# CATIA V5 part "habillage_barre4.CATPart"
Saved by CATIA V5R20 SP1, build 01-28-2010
Part number: habillage_barre4
Bounding box of the stored display mesh (mm): x -20 to 0, y -1003.224 to -170.237, z 31.642 to 358.692
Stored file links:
  C:\Users\patrice\Desktop\IFMa\Semestre 3\IAO\projet iao\iao\habillage_barre4.CATPart
  C:\Users\patrice\Desktop\IFMa\Semestre 3\IAO\projet iao\iao\pcabanel.CATProduct
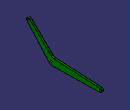
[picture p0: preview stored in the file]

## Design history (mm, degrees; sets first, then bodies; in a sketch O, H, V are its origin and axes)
External parameters (linked from other documents)
  External.AC = 200 mm
Set1
  Plane1: linked copy from another document
  Point1 "C": linked copy from another document
  Point2 "G": linked copy from another document
  Point3 "B": linked copy from another document
Body1 (main body)
  Sketch1 on Plane1, origin (0, 0, 0), H (0, 1, 0), V (0, 0, 1)
    line L1 (-189.8267, 41.8071) -> (-718.3338, 31.6418)
    point P2 (-736.7571, 31.2874)
    line L2 (-748.9992, 45.0596) -> (-998.2085, 325.4151)
    arc A1 centre (-983.2604, 338.7025) radius 20 from (-998.2085, 325.4151) to (-969.3804, 353.102) cw
    point P4 (-983.2604, 338.7025)
    line L3 (-969.3804, 353.102) -> (-726.3262, 118.8166)
    point P6 (-715.5445, 108.4238)
    line L4 (-700.5886, 107.6667) -> (-189.2001, 81.7778)
    arc A2 centre (-190.2113, 61.8034) radius 20 from (-189.2001, 81.7778) to (-189.8267, 41.8071) cw
    point P8 (-190.2113, 61.8034)
    reference projected point E1 (-190.2113, 61.8034) from Point1
    reference projected point E2 (-983.2604, 338.7025) from Point2
    construction line L5 (-715.5445, 108.4238) -> (-736.7571, 31.2874)
    reference projected point E3 (-726.1508, 69.8556) from Point3
    arc A3 centre (-719.1031, 71.6344) radius 40 from (-748.9992, 45.0596) to (-718.3338, 31.6418) ccw
    arc A4 centre (-698.5662, 147.6155) radius 40 from (-726.3262, 118.8166) to (-700.5886, 107.6667) ccw
    radius A1 = 20 {= 0.1*External.AC}
    radius A2 = 20 {= 0.1*External.AC}
    length L5 = 80 {= External.AC /2.5}
    angle L4 L1 = 4
    radius A3 = 40 {= External.AC /5}
    radius A4 = 40 {= External.AC /5}
    radius A3 = 40 (reference)
    tangency: A1 L2, A2 L4, L1 A2, L3 A1, A3 L2, A3 L1, A4 L3, A4 L4
    coincidence: P8 E1, P4 E2, L2 P2, L1 P2, L3 P6, L4 P6
    midpoint: L5 E3
  Pad1: profile Sketch1, direction (-1, 0, 0), length 20 {= External.AC /10}
  Sketch2 on end face of Pad1, origin (-20, -85.2884, 12.611), H (0, 1, 0), V (0, 0, -1)
    point P1 (-104.9229, -49.1924)
    reference projected point E1 (-104.9229, -49.1924) from Point1
    coincidence: P1 E1
  Hole1: placed by Sketch2, at (-20, -190.2113, 61.8034) direction (1, 0, 0), diameter 20 {= External.AC /10}, through (limit type 6)
  Sketch3 on end face of Pad1, origin (-20, -245.8151, 84.6756), H (0, 1, 0), V (0, 0, -1)
    point P1 (-737.4453, -254.0269)
    reference projected point E1 (-737.4453, -254.0269) from Point2
    coincidence: E1 P1
  Hole2: placed by Sketch3, at (-20, -983.2604, 338.7025) direction (1, 0, 0), diameter 20 {= External.AC /10}, through (limit type 6)
  Sketch4 on end face of Pad1, origin (-20, -181.5377, 17.4639), H (0, 1, 0), V (0, 0, -1)
    point P1 (-544.6131, -52.3917)
    reference projected point E1 (-544.6131, -52.3917) from Point3
    coincidence: E1 P1
  Hole3: placed by Sketch4, at (-20, -726.1508, 69.8556) direction (1, 0, 0), diameter 20 {= External.AC /10}, through (limit type 6)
